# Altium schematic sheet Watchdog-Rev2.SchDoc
size Tabloid; Organization: Monterey Bay Aquarium Research Institute; Address1: 7700 Sandholdt Rd; Address2: Moss Landing, CA 95039-9644; CompanyName: MBARI
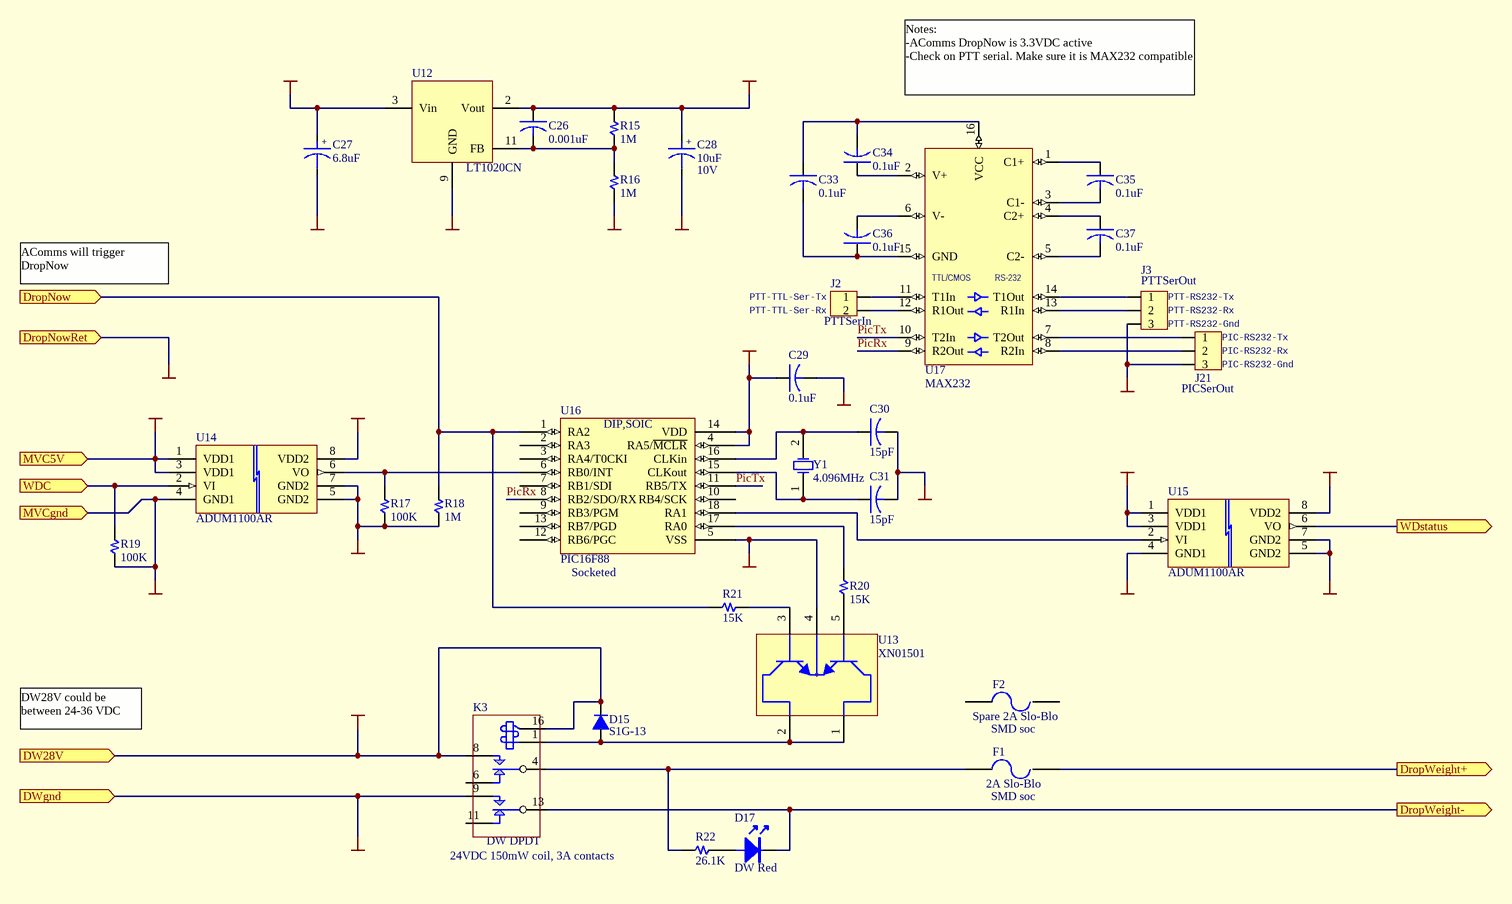
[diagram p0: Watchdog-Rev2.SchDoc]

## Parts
C26  0.001uF  [1206]
C27  6.8uF  [7343pol]
C28  10uF  DescSheet: 10V  [6032pol]
C29  0.1uF  [1206]
C30  15pF  [1206]
C31  15pF  [1206]
C33  0.1uF  [1206]
C34  0.1uF  [1206]
C35  0.1uF  [1206]
C36  0.1uF  [1206]
C37  0.1uF  [1206]
D15  S1G-13  [SMA]
D17  DW Red  [SOT-23]
F1  2A Slo-Blo  DescSheet: SMD soc  [SMF-OMNIBLOK]
F2  Spare 2A Slo-Blo  DescSheet: SMD soc  [SMF-OMNIBLOK]
J2  PTTSerIn  [CGRID2]
J3  PTTSerOut  [CGRID3]
J21  PICSerOut  [CGRID3]
K3  DW DPDT  DescSheet: 24VDC 150mW coil, 3A contacts  [DIP16]
R15  1M  [1206]
R16  1M  [1206]
R17  100K  [1206]
R18  1M  [1206]
R19  100K  [1206]
R20  15K  [1206]
R21  15K  [1206]
R22  26.1K  [1206]
U12  LT1020CN  [DIP14]
U13  XN01501  [SC-74A]
U14  ADUM1100AR  [SO-G8/D5]
U15  ADUM1100AR  [SO-G8/D5]
U16  PIC16F88  DescSheet: Socketed  [DIP18]
U17  MAX232  [SOIC-16-0.15W]
Y1  4.096MHz  [MA-506]

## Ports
DropNow (in), DropNowRet (in), DropWeight+ (out), DropWeight- (out), DW28V (in), DWgnd (in), MVC5V (in), MVCgnd (in), WDC (in), WDstatus (out)

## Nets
DW5V: C26.1 C28.1 C29.1 R15.1 U12.2(Vout) U14.8(VDD2) U15.1(VDD1) U15.3(VDD1) U16.4(RA5/~{MCLR}) U16.14(VDD)
DW28V: C27.1 D15.2(A) K3.8(NO1) K3.16(COIL) U12.3(Vin) ; port DW28V
DWgnd: C27.2 C28.2 C29.2 C30.2 C31.2 J3.3 J21.3 K3.9(NO2) R16.2 R17.2 R18.2 U12.9(GND) U13.4(Emitter) U14.5(GND2) U14.7(GND2) U15.4(GND1) U16.5(VSS) ; port DWgnd, port DropNowRet
MVC5V: U14.1(VDD1) U14.3(VDD1) U15.8(VDD2) ; port MVC5V
MVCgnd: R19.2 U14.4(GND1) U15.5(GND2) U15.7(GND2) ; port MVCgnd
DropNow: R18.1 R21.2 U16.1(RA2) ; port DropNow
DropWeight+: F1.2 ; port DropWeight+
DropWeight-: D17.3(K) K3.13(COMMON2) ; port DropWeight-
PicRx: U16.8(RB2/SDO/RX) U17.9(R2Out)
PicTx: U16.11(RB5/TX) U17.10(T2In)
WDC: R19.1 U14.2(VI) ; port WDC
WDstatus: U15.6(VO) ; port WDstatus
NetC26_2: C26.2 R15.2 R16.1 U12.11(FB)
NetC30_1: C30.1 U16.16(CLKin) Y1.2(OSC2)
NetC31_1: C31.1 U16.15(CLKout) Y1.1(OSC1)
NetC33_1: C33.1 C34.2 U17.16(VCC)
NetC33_2: C33.2 C36.1 U17.15(GND)
NetC34_1: C34.1 U17.2(V+)
NetC35_1: C35.1 U17.1(C1+)
NetC35_2: C35.2 U17.3(C1-)
NetC36_2: C36.2 U17.6(V-)
NetC37_1: C37.1 U17.4(C2+)
NetC37_2: C37.2 U17.5(C2-)
NetD15_1: D15.1(K) K3.1(COIL) U13.1(C1) U13.2(C2)
NetD17_2: D17.2(A) R22.1
NetF1_1: F1.1 K3.4(COMMON1) R22.2
NetJ2_1: J2.1 U17.11(T1In)
NetJ2_2: J2.2 U17.12(R1Out)
NetJ3_1: J3.1 U17.14(T1Out)
NetJ3_2: J3.2 U17.13(R1In)
NetJ21_1: J21.1 U17.7(T2Out)
NetJ21_2: J21.2 U17.8(R2In)
NetR17_1: R17.1 U14.6(VO) U16.6(RB0/INT)
NetR20_1: R20.1 U13.5(B1)
NetR20_2: R20.2 U16.17(RA0)
NetR21_1: R21.1 U13.3(B2)
NetU15_2: U15.2(VI) U16.18(RA1)

Not connected (* = marked no-connect by the designer): F2 1 2; K3 6(NC1) 11(NC2); U16 2(RA3) 3(RA4/T0CKI) 7(RB1/SDI) 9(RB3/PGM) 10(RB4/SCK) 12(RB6/PGC) 13(RB7/PGD)

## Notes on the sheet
- Notes:
  -AComms DropNow is 3.3VDC active
  -Check on PTT serial. Make sure it is MAX232 compatible
- AComms will trigger DropNow
- PTT-TTL-Ser-Tx
- PTT-TTL-Ser-Rx
- PTT-RS232-Tx
- PTT-RS232-Rx
- (near J21) PTT-RS232-Gnd
- (near J21) PIC-RS232-Tx
- (near J21) PIC-RS232-Gnd
- (near J21) PIC-RS232-Rx
- DW28V could be between 24-36 VDC

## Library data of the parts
C26 = CAPACITOR: ManufPartNo: C1206C102K5RACTU; Manufacturer: Kemet; VendorPartNo: 399-1221-1-ND; Cost/ea: 0.132; DescSheet: 10V; Reference: T033, 785; Vendor: Digi-Key
C27 = CAPACITOR POL: Capacitor; ManufPartNo: T491D685M050AS; Manufacturer: Panasonic; VendorPartNo: 399-3109-1-ND; Cost/ea: 0.79; DescSheet: 50V; Reference: T033, 727; Vendor: Digi-Key
C28 = CAPACITOR POL: Capacitor; ManufPartNo: T491C106K010AS; Manufacturer: Panasonic; VendorPartNo: 399-1571-1-ND; Cost/ea: 0.32; Reference: T033, 726; Vendor: Digi-Key
C29 C33-C37 = CAPACITOR: ManufPartNo: C1206C104J5RACTU; Manufacturer: Kemet; VendorPartNo: 399-1250-1-ND; Cost/ea: 0.253; Reference: T033, 785; Vendor: Digi-Key
C30 C31 = CAPACITOR: ManufPartNo: C1206C150J5GACTU; Manufacturer: Kemet; VendorPartNo: 399-1194-1-ND; Cost/ea: 0.171; Reference: T033, 784; Vendor: Digi-Key
D15 = DIODE_S: Diode; Manufacturer: Diodes Inc; VendorPartNo: S1GDICT-ND; Cost/ea: 0.288; DescSheet: 1A, 400V; Reference: T033, 578; Vendor: Digi-Key
D17 = LED: ManufPartNo: SML-LX15SRC-TR; Manufacturer: Lumex; VendorPartNo: 67-1660-1-ND; Cost/ea: 0.494; Reference: T033, 1194; Vendor: Digi-Key
F1 F2 = Fuse 2: Fuse; Manufacturer: Littelfuse; ManufPartNo: 0154002.DRT; VendorPartNo: F1305CT-ND; Cost/ea: 2.63; Reference: T033, 1066; Vendor: Digi-Key
J2 = CON2: Connector; ManufPartNo: 70543-0001; Manufacturer: Molex; VendorPartNo: WM4800-ND; Cost/ea: 0.711; Reference: T033, 94; Vendor: Digi-Key
J3 J21 = CON3: Connector; ManufPartNo: 70543-0002; Manufacturer: Molex; VendorPartNo: WM4801-ND; Cost/ea: 0.89; Reference: T033, 94; Vendor: Digi-Key
K3 = RELAY-PB-V23105: P&B V23105 Relay DPDT; ManufPartNo: V23105A5005A201; VendorPartNo: PB385-ND; Cost/ea: 1.78; Reference: T033, 946; Vendor: Digi-Key
R15 R16 R18 = RESISTOR: ManufPartNo: ERJ-8ENF1004V; Manufacturer: Panasonic; VendorPartNo: P1.00MFCT-ND; Cost/ea: 0.117; Reference: T033, 801; Vendor: Digi-Key
R17 R19 = RESISTOR: ManufPartNo: ERJ-8ENF1003V; Manufacturer: Panasonic; VendorPartNo: P100KFCT-ND; Cost/ea: 0.117; Reference: T033, 801; Vendor: Digi-Key
R20 R21 = RESISTOR: ManufPartNo: ERJ-8ENF1502V; Manufacturer: Panasonic; VendorPartNo: P15.0KFCT-ND; Cost/ea: 0.117; Reference: T033, 801; Vendor: Digi-Key
R22 = RESISTOR: ManufPartNo: ERJ-8ENF2612V; Manufacturer: Panasonic; VendorPartNo: P26.1KFCT-ND; Cost/ea: 0.117; DescSheet: 1/10W; Reference: T033, 801; Vendor: Digi-Key
U12 = LT1020: Micropower Regulator; Manufacturer: Linear Technology; VendorPartNo: LT1020CN-ND; Cost/ea: 6.88; Reference: T033, 463; Vendor: Digi-Key
U13 = XN01501: Dual NPN Common Emitter Transistor; ManufPartNo: XN0150100L; Manufacturer: Panasonic; VendorPartNo: XN0150100LCT-ND; Cost/ea: 0.41; Reference: T033, 529; Vendor: Digi-Key
U14 U15 = ADUM1100AR: Digital Isolator; Manufacturer: Analog Devices; Cost/ea: 4.19; Vendor: Arrow Electronics
U16 = PIC16F88: PIC16F88 microcontroller DIP,SOIC package; ManufPartNo: PIC16F88-I/P; Manufacturer: Microchip; VendorPartNo: PIC16F88-I/P-ND; Cost/ea: 4.58; Reference: T033, 303; Vendor: Digi-Key
U17 = MAX232: MAX232 Communications Chip; ManufPartNo: MAX232ACSE; Manufacturer: Maxim; VendorPartNo: MAX232ACSE-ND; Cost/ea: 5.51; Reference: T033, 483; Vendor: Digi-Key
Y1 = XTAL: Crystal Oscillator; pin to pad: 2>4; Manufacturer: Epson Elec; ManufPartNo: MA-506 4.0960M-C0; VendorPartNo: SE2619CT-ND; Cost/ea: 2.80; Reference: T033, 611; Vendor: Digi-Key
